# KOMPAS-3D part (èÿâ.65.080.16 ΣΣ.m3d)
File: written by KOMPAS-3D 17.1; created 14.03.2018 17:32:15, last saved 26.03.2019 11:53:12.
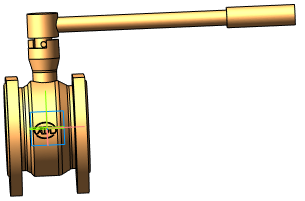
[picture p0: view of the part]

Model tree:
1. Операция без истории:4  (labels: Сталь 20  ГОСТ 1050-2013)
